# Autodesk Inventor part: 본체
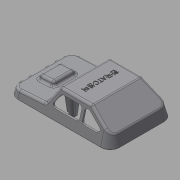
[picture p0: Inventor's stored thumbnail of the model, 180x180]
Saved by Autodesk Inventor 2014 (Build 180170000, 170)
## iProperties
Created: 2015-05
Part Number: 본체
Material: Generic
Document SubType Name: Modeling
Designer: Administrator
Density: 1 g/cm^3
Appearance: Default
Author: Administrator
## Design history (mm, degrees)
sketch "스케치13"
  geometry: L1 (-49, 38)-(49, 38); L2 (61, 26)-(61, -26); L3 (49, -38)-(-49, -38); L4 (-61, -26)-(-61, 26); L5 (-61, 38)-(61, -38); L6 (61, 38)-(-61, -38); A1 r 12 centre (-49, 26) between (-49, 38) and (-61, 26); A2 r 12 centre (-49, -26) between (-61, -26) and (-49, -38); A3 r 12 centre (49, -26) between (49, -38) and (61, -26); A4 r 12 centre (49, 26) between (61, 26) and (49, 38); 1 further point
  constraints: 12 end point, 8 point on circle, 8 point on line, 8 tangent, 4 centre point, 3 equal radius, 2 midpoint, 2 parallel, 1 horizontal, 1 perpendicular
  dimensions: "d63" = 122 distance of L5.end L6.end; "d64" = 76 distance of L6.start L5.end; "d65" = 12 radius of A1
extrude "돌출8" new body sketch "스케치13" distance "d66" = 31; taper "d67" = -15 deg
sketch "스케치16"
  geometry: L1 (-49, 0)-(49, 0) reference; L2 (61, 0)-(52.694, 31) reference; L3 (-61, 0)-(-61, 31); L4 (-31, 31)-(-61, 31); L5 (-61, 0)-(-52.694, 31) reference; L6 (-31, 31)-(-61, 11); L7 (-31, 0)-(-61, 0); L8 (-49, 31)-(49, 31) reference; 1 further point
  constraints: 8 end point, 2 collinear, 2 point on line, 1 perpendicular
  dimensions: "d70" = 20 distance from line of L4 L6.end; "d71" = 30 distance of L4.start L3.end
extrude "돌출9" cut sketch "스케치16" stored distance "d72" = 31; taper "d73" = 0 deg
sketch "스케치17"
  geometry: L1 (61, 0)-(52.694, 31) reference; L2 (-49, 0)-(49, 0) reference; L3 (61, 0)-(58.588, 9); L4 (58.588, 9)-(19, 11.075); L5 (19, 11.075)-(6.549, 31); L6 (49, 31)-(-31, 31) reference; L7 (6.549, 31)-(61, 31); L8 (61, 31)-(61, 0); 1 further point
  constraints: 10 end point, 3 point on line, 1 perpendicular
  dimensions: "d74" = 3 deg angle of L2 L4; "d75" = 125 deg angle of L4 L5; "d76" = 9 distance from line of L2 L3.end; "d77" = 42 horizontal distance of L1.start L4.end
extrude "돌출10" cut sketch "스케치17" stored distance "d78" = 31; taper "d79" = 0 deg
sketch "스케치18"
  geometry: L1 (49, 9.503)-(58.588, 9) reference; L2 (19, 11.075)-(49, 9.503) reference; L3 (61, 0)-(49, 0) reference; L4 (48.444, 14.538)-(50, 9.45); L5 (32.079, 15.396)-(30, 10.498); L6 (32.079, 15.396)-(48.444, 14.538); L7 (30, 10.498)-(50, 9.45); 1 further point
  constraints: 8 end point, 2 point on line, 1 collinear, 1 parallel
  dimensions: "d100" = 11 horizontal distance of L3.start L4.end; "d101" = 20 horizontal distance of L5.end L4.end; "d102" = 70 deg angle of L5 L2; "d103" = 70 deg angle of L1 L4; "d104" = 5 distance between parallel lines of L7 L6
extrude "돌출11" join sketch "스케치18" stored distance "d84" = 26; taper "d85" = 0 deg
fillet "모깎기9" dims "d88" = 3
fillet "모깎기10" dims "d105" = 3
fillet "모깎기11" dims "d106" = 3
feature "쉘2" dims "d112" = 2
sketch "스케치21"
  geometry: L1 (58.929, 26)-(58.929, -26) reference; L2 (49, -35.929)-(-49, -35.929) reference; L3 (-58.929, -26)-(-58.929, 26) reference; L4 (-49, 35.929)-(49, 35.929) reference; L5 (61, 26)-(61, -26) reference; L6 (-49, 38)-(49, 38) reference; L7 (-61, -26)-(-61, 26) reference; L8 (49, -38)-(-49, -38) reference; L9 (59.929, 26)-(59.929, -26); L10 (49, -36.929)-(-49, -36.929); L11 (-59.929, -26)-(-59.929, 26); L12 (-49, 36.929)-(49, 36.929); A1 r 9.929 centre (49, 26) between (58.929, 26) and (49, 35.929) reference; A2 r 9.929 centre (49, -26) between (49, -35.929) and (58.929, -26) reference; A3 r 9.929 centre (-49, -26) between (-58.929, -26) and (-49, -35.929) reference; A4 r 9.929 centre (-49, 26) between (-49, 35.929) and (-58.929, 26) reference; A5 r 12 centre (49, 26) between (61, 26) and (49, 38) reference; A6 r 12 centre (-49, 26) between (-49, 38) and (-61, 26) reference; A7 r 12 centre (-49, -26) between (-61, -26) and (-49, -38) reference; A8 r 12 centre (49, -26) between (49, -38) and (61, -26) reference; A9 r 10.929 centre (49, 26) between (59.929, 26) and (49, 36.929); A10 r 10.929 centre (49, -26) between (49, -36.929) and (59.929, -26); A11 r 10.929 centre (-49, -26) between (-59.929, -26) and (-49, -36.929); A12 r 10.929 centre (-49, 26) between (-49, 36.929) and (-59.929, 26); 1 further point
  constraints: 8 end point, 8 point on circle, 4 centre point, 7 other
  dimensions: "d113" = 1 distance between parallel lines of L4 L12
extrude "돌출14" cut sketch "스케치21" distance "d114" = 1; taper "d115" = 0 deg
sketch "스케치29"
  geometry: L1 (4.886, 31)-(-30.092, 31) reference; L2 (18.172, 12.399)-(7.431, 29.59) reference; L3 (-31.756, 30.496)-(-50.664, 17.891) reference; L4 (10.283, 15.59)-(4.659, 24.59); L5 (2.115, 26)-(-17.849, 26); L6 (-29.486, 26)-(-51.986, 11); L7 (7.739, 11)-(-17.849, 11); L8 (-20.849, 14)-(-20.849, 23); L9 (-51.986, 11)-(-23.986, 11); L10 (-23.986, 11)-(-23.986, 26); L11 (-23.986, 26)-(-29.486, 26); A1 r 3 centre (2.115, 23) between (4.659, 24.59) and (2.115, 26); A2 r 3 centre (7.739, 14) between (7.739, 11) and (10.283, 15.59); A3 r 3 centre (-17.849, 14) between (-20.849, 14) and (-17.849, 11); A4 r 3 centre (-17.849, 23) between (-17.849, 26) and (-20.849, 23); 4 further points
  constraints: 16 end point, 8 point on circle, 8 tangent, 6 point on line, 5 parallel, 4 centre point, 3 equal radius, 3 perpendicular
  dimensions: "d144" = 5 distance between parallel lines of L1 L5; "d145" = 5 distance between parallel lines of L2 L4; "d146" = 34 distance of point (13.151, 11) point (-20.849, 11); "d147" = 15 distance of point (-20.849, 11) point (-20.849, 26); "d148" = 5 distance between parallel lines of L6 L3; "d149" = 15 distance of L9.end L10.end; "d151" = 5 distance from line of L1 L10.end; "d152" = 3 radius of A1; "d153" = 28 distance of L6.end L9.end
sketch "스케치30"
  geometry: L1 (4.886, 31)-(-30.092, 31) reference; L2 (18.172, 12.399)-(7.431, 29.59) reference; L3 (-31.756, 30.496)-(-50.664, 17.891) reference; L4 (-30.242, 25.496)-(-43.742, 16.496); L5 (7.739, 11)-(-17.849, 11); L6 (-20.849, 14)-(-20.849, 23); L7 (10.283, 15.59)-(4.659, 24.59); L8 (2.115, 26)-(-17.849, 26); L9 (-26.986, 26)-(-28.578, 26); L10 (-23.986, 23)-(-23.986, 14); L11 (-26.986, 11)-(-42.078, 11); A1 r 3 centre (2.115, 23) between (4.659, 24.59) and (2.115, 26); A2 r 3 centre (7.739, 14) between (7.739, 11) and (10.283, 15.59); A3 r 3 centre (-17.849, 14) between (-20.849, 14) and (-17.849, 11); A4 r 3 centre (-17.849, 23) between (-17.849, 26) and (-20.849, 23); A5 r 3 centre (-26.986, 23) between (-23.986, 23) and (-26.986, 26); A6 r 3 centre (-28.578, 23) between (-28.578, 26) and (-30.242, 25.496); A7 r 3 centre (-26.986, 14) between (-26.986, 11) and (-23.986, 14); A8 r 3 centre (-42.078, 14) between (-43.742, 16.496) and (-42.078, 11); 7 further points
  constraints: 16 end point, 16 point on circle, 16 tangent, 13 point on line, 8 centre point, 6 equal radius, 4 parallel, 3 perpendicular, 1 collinear
  dimensions: "d154" = 34 distance of point (13.151, 11) point (-20.849, 11); "d155" = 15 distance of point (-20.849, 11) point (-20.849, 26); "d158" = 5 distance between parallel lines of L1 L8; "d159" = 5 distance between parallel lines of L2 L7; "d160" = 3 radius of A1; "d161" = 5 distance between parallel lines of L4 L3; "d162" = 28 distance of point (-23.986, 11) point (-51.986, 11); "d163" = 15 distance of point (-23.986, 26) point (-23.986, 11); "d164" = 3 radius of A5
extrude "돌출17" cut sketch "스케치30" stored distance "d165" = 1; taper "d166" = 0 deg
node "작업 평면3"
sketch "스케치32"
  geometry: L1 (60.732, -26)-(57.704, -26) reference; L2 (49, -37.732)-(49, -33.667) reference; L3 (26.986, -31.033)-(28.578, -31.033) reference; L4 (30.242, -31.168)-(43.742, -33.58) reference; L5 (42.078, -35.053)-(26.986, -35.053) reference; L6 (23.986, -34.249)-(23.986, -31.837) reference; L7 (-10.283, -33.823)-(-4.659, -31.411) reference; L8 (-2.115, -31.033)-(17.849, -31.033) reference; L9 (20.849, -31.837)-(20.849, -34.249) reference; L10 (17.849, -35.053)-(-7.739, -35.053) reference; L11 (-49, -37.732)-(49, -37.732) reference; L12 (49, -37.732)-(49, -33.667) reference; L13 (30.092, -30.289)-(49, -33.667) reference; L14 (-4.886, -30.289)-(30.092, -30.289) reference; L15 (-15.628, -34.896)-(-4.886, -30.289) reference; L16 (-49, -36.051)-(-20.403, -35.649) reference; L17 (-49, -37.732)-(-49, -36.051) reference; L18 (-49, -37.732)-(-49, -36.051) reference; L19 (-60.732, -26)-(-59.153, -26) reference; L20 (-60.732, 26)-(-60.732, -26) reference; L21 (-60.732, -26)-(-59.153, -26) reference; L22 (-59.153, 26)-(-59.153, -26) reference; L23 (-60.732, 26)-(-59.153, 26) reference; L24 (-60.732, 26)-(-59.153, 26) reference; L25 (-49, 37.732)-(-49, 36.051) reference; L26 (-20.403, 35.649)-(-49, 36.051) reference; L27 (23.986, 31.837)-(23.986, 34.249) reference; L28 (26.986, 35.053)-(42.078, 35.053) reference; L29 (43.742, 33.58)-(30.242, 31.168) reference; L30 (28.578, 31.033)-(26.986, 31.033) reference; L31 (-7.739, 35.053)-(17.849, 35.053) reference; L32 (20.849, 34.249)-(20.849, 31.837) reference; L33 (17.849, 31.033)-(-2.115, 31.033) reference; L34 (-4.659, 31.411)-(-10.283, 33.823) reference; L35 (49, 37.732)-(-49, 37.732) reference; L36 (-49, 37.732)-(-49, 36.051) reference; L37 (-20.403, 35.649)-(-49, 36.051) reference; L38 (-4.886, 30.289)-(-15.628, 34.896) reference; L39 (30.092, 30.289)-(-4.886, 30.289) reference; L40 (49, 33.667)-(30.092, 30.289) reference; L41 (49, 37.732)-(49, 33.667) reference; L42 (49, 37.732)-(49, 33.667) reference; L43 (60.732, 26)-(57.704, 26) reference; L44 (60.732, -26)-(60.732, 26) reference; L45 (60.732, 26)-(57.704, 26) reference; L46 (57.704, -26)-(57.704, 26) reference; L47 (60.732, -26)-(57.704, -26) reference; C1 r 3 at (-40.268, 0); C2 r 3 at (-0.268, -22); C3 r 3 at (-0.268, 22); C4 r 3 at (39.732, 0); A1 r 11.732 centre (49, -26) between (49, -37.732) and (60.732, -26) reference; A2 r 11.732 centre (-49, -26) between (-60.732, -26) and (-49, -37.732) reference; A3 r 11.732 centre (-49, 26) between (-49, 37.732) and (-60.732, 26) reference; A4 r 11.732 centre (49, 26) between (60.732, 26) and (49, 37.732) reference; 19 further points; 18 other entities
  constraints: 4 centre point, 2 horizontal alignment, 1 vertical alignment, 22 other
  dimensions: "d168" = 6 diameter of C2; "d169" = 6 diameter of C3; "d170" = 6 diameter of C4; "d171" = 6 diameter of C1; "d172" = 44 distance of C3.centre C2.centre; "d173" = 22 vertical distance of point (0, 0) C2.centre; "d174" = 21 distance from line of L44 C4.centre; "d175" = 40 horizontal distance of C3.centre C4.centre; "d176" = 40 horizontal distance of C1.centre C3.centre
extrude "돌출18" join sketch "스케치32" stored distance "d177" = 1; taper "d178" = 4 deg
node "작업 평면4"
sketch "스케치34"
  geometry: L1 (-45, 23)-(-35, 23); L2 (-35, 23)-(-35, 21); L3 (-35, 21)-(-45, 21); L4 (-45, 21)-(-45, 23); L5 (-45, 23)-(-35, 21); L6 (-35, 23)-(-45, 21); L7 (-84.789, 1)-(-74.789, 1); L8 (-74.789, 1)-(-74.789, -1); L9 (-74.789, -1)-(-84.789, -1); L10 (-84.789, -1)-(-84.789, 1); L11 (-84.789, 1)-(-74.789, -1); L12 (-74.789, 1)-(-84.789, -1); L13 (-45, -21)-(-35, -21); L14 (-35, -21)-(-35, -23); L15 (-35, -23)-(-45, -23); L16 (-45, -23)-(-45, -21); L17 (-45, -21)-(-35, -23); L18 (-35, -21)-(-45, -23); L19 (-5.014, 1)-(4.986, 1); L20 (4.986, 1)-(4.986, -1); L21 (4.986, -1)-(-5.014, -1); L22 (-5.014, -1)-(-5.014, 1); L23 (-5.014, 1)-(4.986, -1); L24 (4.986, 1)-(-5.014, -1); C1 r 3 at (-40, 22) reference; C2 r 3 at (-40, -22) reference; C3 r 3 at (-80, 0) reference; A1 r 4.958 centre (-40, 22) between (-35.382, 23.803) and (-35.382, 20.197) reference; A2 r 4.958 centre (-40, -22) between (-35.382, -20.197) and (-35.382, -23.803) reference; 3 further points; 2 other entities
  constraints: 48 end point, 8 midpoint, 8 parallel, 4 horizontal, 4 perpendicular, 2 vertical alignment, 2 other
  dimensions: "d180" = 10 distance of L2.end L3.end; "d181" = 2 distance of L1.end L2.end; "d182" = 10 distance of L20.end L21.end; "d183" = 2 distance of L19.end L20.end; "d184" = 10 distance of L8.end L9.end; "d185" = 2 distance of L9.end L7.start; "d186" = 10 distance of L14.end L15.end; "d187" = 2 distance of L15.end L13.start
extrude "돌출19" join sketch "스케치34" stored distance "d188" = 1; taper "d189" = 5 deg
sketch "스케치35"
  geometry: L1 (60.732, -26)-(60.732, 26) reference; 2 further points
  constraints: 1 horizontal alignment, 1 other
  dimensions: "d190" = 50 distance from line of L1 point (10.732, 0)
feature "엠보싱1" sketch "스케치35" dims "d63" = 122, "d64" = 76, "d65" = 12, "d191" = 0.5, "d192" = 0
node "작업 평면5"
sketch "스케치36"
  geometry: A1 r 4 centre (21, 1) between (25, 1) and (17, 1); A2 r 4 centre (10, 1) between (14, 1) and (6, 1); A3 r 4 centre (-10, 1) between (-6, 1) and (-14, 1); A4 r 4 centre (-21, 1) between (-17, 1) and (-25, 1); 3 further points
  constraints: 8 point on circle, 4 centre point, 13 other
  dimensions: "d194" = 8 diameter of A1; "d195" = 8 diameter of A2; "d196" = 8 diameter of A3; "d197" = 8 diameter of A4; "d198" = 20 distance of A2.centre A3.centre; "d199" = 10 horizontal distance of point (0, 0) A3.centre; "d200" = 11 distance of A3.centre A4.centre; "d201" = 11 distance of A2.centre A1.centre
extrude "돌출20" join sketch "스케치36" stored distance "d202" = 0; taper "d203" = 0 deg
chamfer "모따기1" distance "d204" = 1; stored, may be unused: second distance "d205" = 2, angle "d206" = 45 deg
node "솔리드3"
node "투영된 루프17"
node "투영된 루프18"
node "투영된 루프19"
node "투영된 루프20"
node "투영된 루프21"
node "투영된 루프22"
node "투영된 루프23"
node "투영된 루프24"
node "투영된 루프25"
node "투영된 루프26"
node "투영된 루프27"
other parameters: "d53" = 70 deg, "d156" = 5, "d157" = 5, "d167" = 1, "d179" = -2, "d193" = -63
